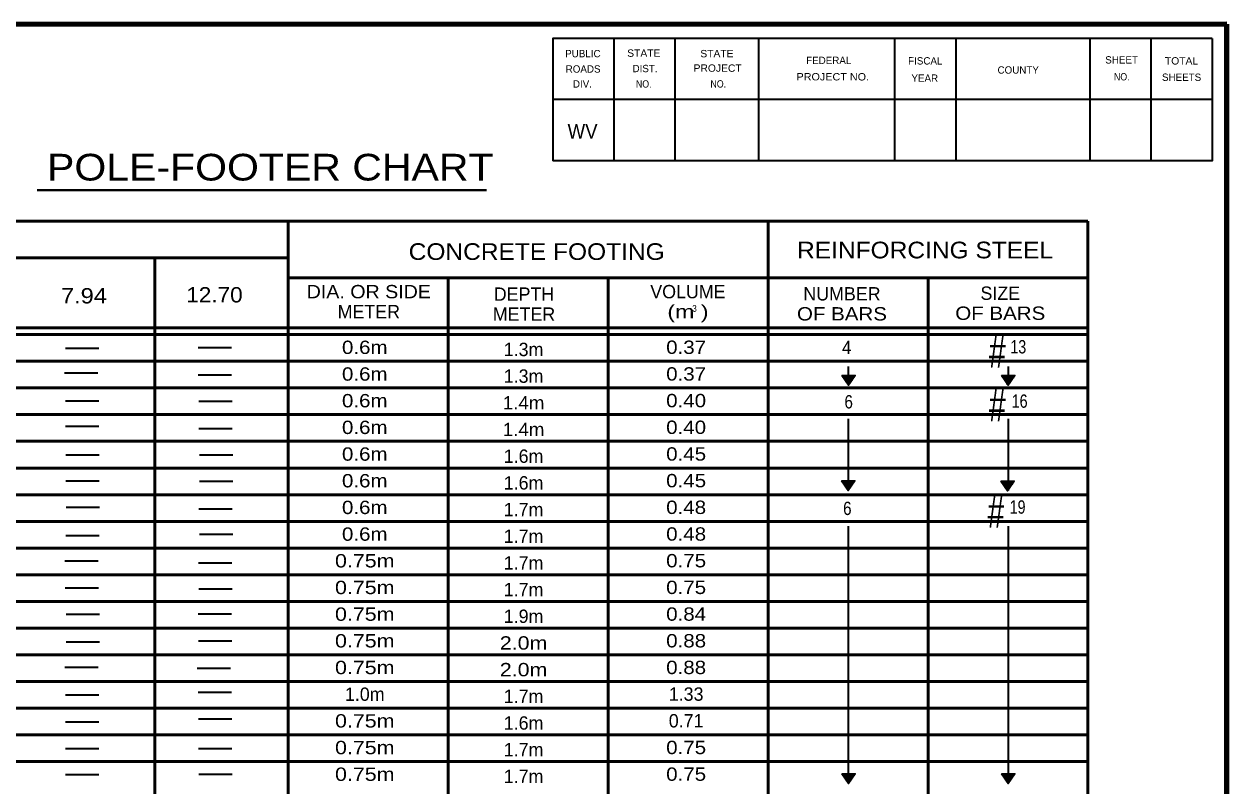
# Model space of a CAD drawing. Extents: x -711 to 145, y 25 to 569.
# Drawn here: x -112 to 138.1, y 404.4 to 562.7 of the extents above; entities that cross this region are included whole.
import ezdxf
from ezdxf.enums import TextEntityAlignment as Align

# ---------------------------------------------------------------- set-up
doc = ezdxf.new("R2010")
doc.units = 0
doc.header["$LTSCALE"] = 1.1
doc.layers.add('1', color=7, linetype='Continuous', lineweight=53)
doc.layers.add('61', color=7, linetype='Continuous', lineweight=35)

msp = doc.modelspace()

# ---------------------------------------------------------------- linework, layer by layer
at = {"layer": '1', "lineweight": 158}
msp.add_line((138.105, 36.575), (138.105, 562.675), dxfattribs=at)
at = {"layer": '1', "lineweight": 13}
msp.add_line((138.105, 36.575), (138.105, 562.675), dxfattribs=at)
at = {"layer": '1', "lineweight": 40}
msp.add_line((-109.311, 528.153), (-15.861, 528.153), dxfattribs=at)
at = {"layer": '1'}
for p, q in [((-251.147, 521.717), (-44.796, 521.717)), ((-57.107, 521.717), (-57.107, 281.939)), ((-57.097, 521.717), (109.213, 521.717)), ((42.685, 521.717), (42.685, 281.939)), ((109.213, 521.717), (109.213, 281.939)), ((-251.147, 514.094), (-57.107, 514.094)), ((-84.827, 514.094), (-84.827, 281.939)), ((-57.107, 509.936), (109.213, 509.936)), ((-23.843, 509.936), (-23.843, 281.939)), ((9.421, 509.936), (9.421, 281.939)), ((75.949, 509.936), (75.949, 281.939)), ((-251.147, 499.541), (109.194, 499.541)), ((-251.147, 498.155), (109.194, 498.155)), ((-251.147, 492.611), (109.194, 492.611)), ((-251.147, 487.067), (109.194, 487.067)), ((-251.147, 481.523), (109.194, 481.523)), ((-251.147, 475.979), (109.194, 475.979)), ((-251.147, 470.435), (109.194, 470.435)), ((-251.147, 464.891), (109.194, 464.891)), ((-251.147, 459.347), (109.194, 459.347)), ((-251.147, 453.803), (109.194, 453.803)), ((-251.147, 448.259), (109.194, 448.259)), ((-251.147, 442.715), (109.194, 442.715)), ((-251.147, 437.171), (109.194, 437.171)), ((-251.147, 431.627), (109.194, 431.627)), ((-251.147, 426.083), (109.194, 426.083)), ((-251.147, 420.539), (109.194, 420.539)), ((-251.147, 414.995), (109.194, 414.995)), ((-251.147, 409.451), (109.194, 409.451))]:
    msp.add_line(p, q, dxfattribs=at)
at = {"layer": '1', "lineweight": 35}
for p, q in [((-103.41, 495.341), (-96.48, 495.341)), ((-75.797, 495.447), (-68.867, 495.447)), ((59.317, 491.516), (59.317, 488.084)), ((92.581, 491.516), (92.581, 488.084)), ((-103.584, 490.23), (-96.654, 490.23)), ((-75.797, 489.804), (-68.867, 489.804)), ((-103.373, 484.373), (-96.443, 484.373)), ((-75.658, 484.339), (-68.728, 484.339)), ((59.317, 480.647), (59.317, 465.773)), ((92.581, 480.647), (92.581, 465.773)), ((-103.369, 479.156), (-96.439, 479.156)), ((-75.658, 478.659), (-68.728, 478.659)), ((-103.301, 473.16), (-96.371, 473.16)), ((-75.519, 473.16), (-68.589, 473.16)), ((-103.339, 467.766), (-96.409, 467.766)), ((-75.519, 467.728), (-68.589, 467.728)), ((-103.23, 462.301), (-96.3, 462.301)), ((-75.692, 461.981), (-68.762, 461.981)), ((59.317, 458.336), (59.317, 404.848)), ((92.581, 458.336), (92.581, 404.848)), ((-103.301, 456.444), (-96.371, 456.444)), ((-75.553, 456.692), (-68.623, 456.692)), ((-103.516, 451.155), (-96.586, 451.155)), ((-75.73, 450.73), (-68.8, 450.73)), ((-103.478, 445.513), (-96.548, 445.513)), ((-75.658, 445.303), (-68.728, 445.303)), ((-103.234, 440.048), (-96.304, 440.048)), ((-75.835, 440.119), (-68.905, 440.119)), ((-103.234, 434.3), (-96.304, 434.3)), ((-75.73, 434.511), (-68.8, 434.511)), ((-103.55, 429.046), (-96.62, 429.046)), ((-76.046, 428.835), (-69.116, 428.835)), ((-103.41, 423.298), (-96.48, 423.298)), ((-75.835, 423.862), (-68.905, 423.862)), ((-75.764, 418.325), (-68.834, 418.325)), ((-103.407, 417.69), (-96.477, 417.69)), ((-103.41, 412.153), (-96.48, 412.153)), ((-75.767, 412.153), (-68.837, 412.153)), ((-103.41, 406.755), (-96.48, 406.755)), ((-75.696, 406.793), (-68.766, 406.793))]:
    msp.add_line(p, q, dxfattribs=at)
at = {"layer": '1', "lineweight": 158}
msp.add_lwpolyline([(138.105, 562.675), (-653.595, 562.575), (-653.495, 36.575)], dxfattribs=at)
at = {"layer": '1', "lineweight": 35}
for points in [[(58.038, 489.639), (60.81, 489.639), (59.424, 487.626)], [(91.203, 489.639), (93.975, 489.639), (92.589, 487.626)], [(57.944, 467.781), (60.716, 467.781), (59.33, 465.768)], [(91.109, 467.687), (93.88, 467.687), (92.495, 465.674)], [(58.038, 406.916), (60.81, 406.916), (59.424, 404.903)], [(91.203, 406.916), (93.975, 406.916), (92.589, 404.903)]]:
    msp.add_lwpolyline(points, close=True, dxfattribs=at)
for points in [[(58.297, 489.441), (58.721, 489.488), (59.381, 489.347), (59.852, 489.441), (60.04, 489.441), (60.323, 489.535), (60.511, 489.488), (59.664, 489.3), (59.287, 489.629), (59.334, 489.3), (59.334, 489.394), (59.758, 489.535), (60.276, 489.535), (60.182, 489.441), (59.192, 489.488), (58.816, 489.441), (58.58, 489.347), (58.768, 489.205), (58.863, 489.017), (58.957, 488.829), (59.004, 488.687), (59.145, 488.499), (59.569, 488.169), (59.569, 487.886), (59.428, 488.169), (59.334, 488.405), (59.145, 488.64), (58.957, 488.876), (58.674, 489.111), (58.486, 489.441), (58.674, 489.158), (58.768, 488.829), (58.91, 488.64), (59.004, 488.546), (59.239, 488.405), (59.381, 488.31), (59.475, 488.122), (59.522, 488.075), (59.381, 488.122), (59.239, 488.357), (59.239, 488.122), (59.758, 488.263), (60.464, 489.488), (60.511, 489.488), (60.464, 489.3), (60.276, 488.97), (60.087, 488.687), (60.04, 488.687), (59.852, 488.357), (59.71, 488.075), (59.569, 487.886), (59.475, 487.886), (60.559, 489.488), (60.511, 489.347), (60.653, 489.441), (60.464, 489.205), (60.182, 488.876), (60.04, 488.781), (59.852, 488.452), (59.758, 488.405), (59.616, 488.593), (59.428, 488.593), (59.239, 488.593), (59.569, 488.31), (59.522, 488.452), (59.287, 488.31), (59.758, 488.923), (59.664, 488.734), (59.616, 488.64), (59.428, 488.64), (59.239, 488.781), (59.192, 489.064), (59.098, 489.158), (59.004, 489.252), (59.475, 489.394), (59.664, 489.111), (59.71, 489.205), (59.334, 489.017), (59.569, 489.064), (59.852, 489.252), (59.946, 489.158), (59.616, 488.876), (59.616, 489.158), (59.428, 489.347), (59.004, 489.205), (58.91, 488.64), (59.475, 489.111), (59.71, 489.064), (59.852, 489.158), (59.993, 489.3), (59.805, 488.829), (59.758, 488.546), (60.087, 488.97), (59.852, 488.923), (60.135, 489.3), (59.993, 489.111), (59.946, 489.064), (59.664, 488.781), (59.616, 488.829), (59.522, 489.017), (59.475, 489.252)], [(59.475, 489.252), (59.145, 489.017), (59.334, 488.876), (58.768, 489.205), (58.768, 489.3), (59.051, 488.829), (59.522, 488.876), (59.287, 488.734), (59.569, 488.781), (59.993, 489.205), (60.229, 489.252), (60.229, 489.3), (60.087, 489.017), (59.664, 488.499), (59.569, 488.122), (58.863, 489.252), (58.863, 489.441), (58.957, 489.252), (58.863, 488.687), (59.381, 488.405), (59.192, 487.933), (59.428, 488.028), (59.239, 488.64), (59.852, 489.252), (59.334, 489.111)], [(91.462, 489.441), (91.886, 489.488), (92.545, 489.347), (93.016, 489.441), (93.205, 489.441), (93.488, 489.535), (93.676, 489.488), (92.828, 489.3), (92.451, 489.629), (92.498, 489.3), (92.498, 489.394), (92.922, 489.535), (93.44, 489.535), (93.346, 489.441), (92.357, 489.488), (91.98, 489.441), (91.744, 489.347), (91.933, 489.205), (92.027, 489.017), (92.121, 488.829), (92.168, 488.687), (92.31, 488.499), (92.734, 488.169), (92.734, 487.886), (92.592, 488.169), (92.498, 488.405), (92.31, 488.64), (92.121, 488.876), (91.839, 489.111), (91.65, 489.441), (91.839, 489.158), (91.933, 488.829), (92.074, 488.64), (92.168, 488.546), (92.404, 488.405), (92.545, 488.31), (92.639, 488.122), (92.687, 488.075), (92.545, 488.122), (92.404, 488.357), (92.404, 488.122), (92.922, 488.263), (93.629, 489.488), (93.676, 489.488), (93.629, 489.3), (93.44, 488.97), (93.252, 488.687), (93.205, 488.687), (93.016, 488.357), (92.875, 488.075), (92.734, 487.886), (92.639, 487.886), (93.723, 489.488), (93.676, 489.347), (93.817, 489.441), (93.629, 489.205), (93.346, 488.876), (93.205, 488.781), (93.016, 488.452), (92.922, 488.405), (92.781, 488.593), (92.592, 488.593), (92.404, 488.593), (92.734, 488.31), (92.687, 488.452), (92.451, 488.31), (92.922, 488.923), (92.828, 488.734), (92.781, 488.64), (92.592, 488.64), (92.404, 488.781), (92.357, 489.064), (92.263, 489.158), (92.168, 489.252), (92.639, 489.394), (92.828, 489.111), (92.875, 489.205), (92.498, 489.017), (92.734, 489.064), (93.016, 489.252), (93.111, 489.158), (92.781, 488.876), (92.781, 489.158), (92.592, 489.347), (92.168, 489.205), (92.074, 488.64), (92.639, 489.111), (92.875, 489.064), (93.016, 489.158), (93.158, 489.3), (92.969, 488.829), (92.922, 488.546), (93.252, 488.97), (93.016, 488.923), (93.299, 489.3), (93.158, 489.111), (93.111, 489.064), (92.828, 488.781), (92.781, 488.829), (92.687, 489.017), (92.639, 489.252)], [(92.639, 489.252), (92.31, 489.017), (92.498, 488.876), (91.933, 489.205), (91.933, 489.3), (92.215, 488.829), (92.687, 488.876), (92.451, 488.734), (92.734, 488.781), (93.158, 489.205), (93.393, 489.252), (93.393, 489.3), (93.252, 489.017), (92.828, 488.499), (92.734, 488.122), (92.027, 489.252), (92.027, 489.441), (92.121, 489.252), (92.027, 488.687), (92.545, 488.405), (92.357, 487.933), (92.592, 488.028), (92.404, 488.64), (93.016, 489.252), (92.498, 489.111)], [(58.203, 467.582), (58.627, 467.63), (59.287, 467.488), (59.758, 467.582), (59.946, 467.582), (60.229, 467.677), (60.417, 467.63), (59.569, 467.441), (59.192, 467.771), (59.239, 467.441), (59.239, 467.535), (59.663, 467.677), (60.182, 467.677), (60.087, 467.582), (59.098, 467.63), (58.721, 467.582), (58.486, 467.488), (58.674, 467.347), (58.768, 467.159), (58.863, 466.97), (58.91, 466.829), (59.051, 466.64), (59.475, 466.311), (59.475, 466.028), (59.334, 466.311), (59.239, 466.546), (59.051, 466.782), (58.863, 467.017), (58.58, 467.253), (58.391, 467.582), (58.58, 467.3), (58.674, 466.97), (58.816, 466.782), (58.91, 466.687), (59.145, 466.546), (59.287, 466.452), (59.381, 466.263), (59.428, 466.216), (59.287, 466.263), (59.145, 466.499), (59.145, 466.263), (59.663, 466.405), (60.37, 467.63), (60.417, 467.63), (60.37, 467.441), (60.182, 467.111), (59.993, 466.829), (59.946, 466.829), (59.758, 466.499), (59.616, 466.216), (59.475, 466.028), (59.381, 466.028), (60.464, 467.63), (60.417, 467.488), (60.559, 467.582), (60.37, 467.347), (60.087, 467.017), (59.946, 466.923), (59.758, 466.593), (59.663, 466.546), (59.522, 466.735), (59.334, 466.735), (59.145, 466.735), (59.475, 466.452), (59.428, 466.593), (59.192, 466.452), (59.663, 467.064), (59.569, 466.876), (59.522, 466.782), (59.334, 466.782), (59.145, 466.923), (59.098, 467.206), (59.004, 467.3), (58.91, 467.394), (59.381, 467.535), (59.569, 467.253), (59.616, 467.347), (59.239, 467.159), (59.475, 467.206), (59.758, 467.394), (59.852, 467.3), (59.522, 467.017), (59.522, 467.3), (59.334, 467.488), (58.91, 467.347), (58.816, 466.782), (59.381, 467.253), (59.616, 467.206), (59.758, 467.3), (59.899, 467.441), (59.71, 466.97), (59.663, 466.687), (59.993, 467.111), (59.758, 467.064), (60.04, 467.441), (59.899, 467.253), (59.852, 467.206), (59.569, 466.923), (59.522, 466.97), (59.428, 467.159), (59.381, 467.394)], [(59.381, 467.394), (59.051, 467.159), (59.239, 467.017), (58.674, 467.347), (58.674, 467.441), (58.957, 466.97), (59.428, 467.017), (59.192, 466.876), (59.475, 466.923), (59.899, 467.347), (60.135, 467.394), (60.135, 467.441), (59.993, 467.159), (59.569, 466.64), (59.475, 466.263), (58.768, 467.394), (58.768, 467.582), (58.863, 467.394), (58.768, 466.829), (59.287, 466.546), (59.098, 466.075), (59.334, 466.169), (59.145, 466.782), (59.758, 467.394), (59.239, 467.253)], [(91.368, 467.488), (91.791, 467.535), (92.451, 467.394), (92.922, 467.488), (93.111, 467.488), (93.393, 467.582), (93.582, 467.535), (92.734, 467.347), (92.357, 467.677), (92.404, 467.347), (92.404, 467.441), (92.828, 467.582), (93.346, 467.582), (93.252, 467.488), (92.263, 467.535), (91.886, 467.488), (91.65, 467.394), (91.839, 467.253), (91.933, 467.064), (92.027, 466.876), (92.074, 466.735), (92.216, 466.546), (92.639, 466.216), (92.639, 465.934), (92.498, 466.216), (92.404, 466.452), (92.216, 466.687), (92.027, 466.923), (91.744, 467.159), (91.556, 467.488), (91.744, 467.206), (91.839, 466.876), (91.98, 466.687), (92.074, 466.593), (92.31, 466.452), (92.451, 466.358), (92.545, 466.169), (92.593, 466.122), (92.451, 466.169), (92.31, 466.405), (92.31, 466.169), (92.828, 466.311), (93.535, 467.535), (93.582, 467.535), (93.535, 467.347), (93.346, 467.017), (93.158, 466.735), (93.111, 466.735), (92.922, 466.405), (92.781, 466.122), (92.639, 465.934), (92.545, 465.934), (93.629, 467.535), (93.582, 467.394), (93.723, 467.488), (93.535, 467.253), (93.252, 466.923), (93.111, 466.829), (92.922, 466.499), (92.828, 466.452), (92.687, 466.64), (92.498, 466.64), (92.31, 466.64), (92.639, 466.358), (92.593, 466.499), (92.357, 466.358), (92.828, 466.97), (92.734, 466.782), (92.687, 466.687), (92.498, 466.687), (92.31, 466.829), (92.263, 467.111), (92.169, 467.206), (92.074, 467.3), (92.545, 467.441), (92.734, 467.159), (92.781, 467.253), (92.404, 467.064), (92.639, 467.111), (92.922, 467.3), (93.016, 467.206), (92.687, 466.923), (92.687, 467.206), (92.498, 467.394), (92.074, 467.253), (91.98, 466.687), (92.545, 467.159), (92.781, 467.111), (92.922, 467.206), (93.064, 467.347), (92.875, 466.876), (92.828, 466.593), (93.158, 467.017), (92.922, 466.97), (93.205, 467.347), (93.064, 467.159), (93.016, 467.111), (92.734, 466.829), (92.687, 466.876), (92.593, 467.064), (92.545, 467.3)], [(92.545, 467.3), (92.216, 467.064), (92.404, 466.923), (91.839, 467.253), (91.839, 467.347), (92.121, 466.876), (92.593, 466.923), (92.357, 466.782), (92.639, 466.829), (93.064, 467.253), (93.299, 467.3), (93.299, 467.347), (93.158, 467.064), (92.734, 466.546), (92.639, 466.169), (91.933, 467.3), (91.933, 467.488), (92.027, 467.3), (91.933, 466.735), (92.451, 466.452), (92.263, 465.981), (92.498, 466.075), (92.31, 466.687), (92.922, 467.3), (92.404, 467.159)], [(58.297, 406.718), (58.721, 406.765), (59.381, 406.624), (59.852, 406.718), (60.04, 406.718), (60.323, 406.812), (60.511, 406.765), (59.664, 406.577), (59.287, 406.906), (59.334, 406.577), (59.334, 406.671), (59.758, 406.812), (60.276, 406.812), (60.182, 406.718), (59.192, 406.765), (58.816, 406.718), (58.58, 406.624), (58.768, 406.482), (58.863, 406.294), (58.957, 406.106), (59.004, 405.964), (59.145, 405.776), (59.569, 405.446), (59.569, 405.163), (59.428, 405.446), (59.334, 405.682), (59.145, 405.917), (58.957, 406.153), (58.674, 406.388), (58.486, 406.718), (58.674, 406.435), (58.768, 406.106), (58.91, 405.917), (59.004, 405.823), (59.239, 405.682), (59.381, 405.587), (59.475, 405.399), (59.522, 405.352), (59.381, 405.399), (59.239, 405.634), (59.239, 405.399), (59.758, 405.54), (60.464, 406.765), (60.511, 406.765), (60.464, 406.577), (60.276, 406.247), (60.087, 405.964), (60.04, 405.964), (59.852, 405.634), (59.71, 405.352), (59.569, 405.163), (59.475, 405.163), (60.559, 406.765), (60.511, 406.624), (60.653, 406.718), (60.464, 406.482), (60.182, 406.153), (60.04, 406.058), (59.852, 405.729), (59.758, 405.682), (59.616, 405.87), (59.428, 405.87), (59.239, 405.87), (59.569, 405.587), (59.522, 405.729), (59.287, 405.587), (59.758, 406.2), (59.664, 406.011), (59.616, 405.917), (59.428, 405.917), (59.239, 406.058), (59.192, 406.341), (59.098, 406.435), (59.004, 406.53), (59.475, 406.671), (59.664, 406.388), (59.71, 406.482), (59.334, 406.294), (59.569, 406.341), (59.852, 406.53), (59.946, 406.435), (59.616, 406.153), (59.616, 406.435), (59.428, 406.624), (59.004, 406.482), (58.91, 405.917), (59.475, 406.388), (59.71, 406.341), (59.852, 406.435), (59.993, 406.577), (59.805, 406.106), (59.758, 405.823), (60.087, 406.247), (59.852, 406.2), (60.135, 406.577), (59.993, 406.388), (59.946, 406.341), (59.664, 406.058), (59.616, 406.106), (59.522, 406.294), (59.475, 406.53)], [(59.475, 406.53), (59.145, 406.294), (59.334, 406.153), (58.768, 406.482), (58.768, 406.577), (59.051, 406.106), (59.522, 406.153), (59.287, 406.011), (59.569, 406.058), (59.993, 406.482), (60.229, 406.53), (60.229, 406.577), (60.087, 406.294), (59.664, 405.776), (59.569, 405.399), (58.863, 406.53), (58.863, 406.718), (58.957, 406.53), (58.863, 405.964), (59.381, 405.682), (59.192, 405.211), (59.428, 405.305), (59.239, 405.917), (59.852, 406.53), (59.334, 406.388)], [(91.462, 406.718), (91.886, 406.765), (92.545, 406.624), (93.016, 406.718), (93.205, 406.718), (93.488, 406.812), (93.676, 406.765), (92.828, 406.577), (92.451, 406.906), (92.498, 406.577), (92.498, 406.671), (92.922, 406.812), (93.44, 406.812), (93.346, 406.718), (92.357, 406.765), (91.98, 406.718), (91.745, 406.624), (91.933, 406.482), (92.027, 406.294), (92.121, 406.106), (92.169, 405.964), (92.31, 405.776), (92.734, 405.446), (92.734, 405.163), (92.593, 405.446), (92.498, 405.682), (92.31, 405.917), (92.121, 406.153), (91.839, 406.388), (91.65, 406.718), (91.839, 406.435), (91.933, 406.106), (92.074, 405.917), (92.169, 405.823), (92.404, 405.682), (92.545, 405.587), (92.639, 405.399), (92.687, 405.352), (92.545, 405.399), (92.404, 405.634), (92.404, 405.399), (92.922, 405.54), (93.629, 406.765), (93.676, 406.765), (93.629, 406.577), (93.44, 406.247), (93.252, 405.964), (93.205, 405.964), (93.016, 405.634), (92.875, 405.352), (92.734, 405.163), (92.639, 405.163), (93.723, 406.765), (93.676, 406.624), (93.817, 406.718), (93.629, 406.482), (93.346, 406.153), (93.205, 406.058), (93.016, 405.729), (92.922, 405.682), (92.781, 405.87), (92.593, 405.87), (92.404, 405.87), (92.734, 405.587), (92.687, 405.729), (92.451, 405.587), (92.922, 406.2), (92.828, 406.011), (92.781, 405.917), (92.593, 405.917), (92.404, 406.058), (92.357, 406.341), (92.263, 406.435), (92.169, 406.53), (92.639, 406.671), (92.828, 406.388), (92.875, 406.482), (92.498, 406.294), (92.734, 406.341), (93.016, 406.53), (93.111, 406.435), (92.781, 406.153), (92.781, 406.435), (92.593, 406.624), (92.169, 406.482), (92.074, 405.917), (92.639, 406.388), (92.875, 406.341), (93.016, 406.435), (93.158, 406.577), (92.969, 406.106), (92.922, 405.823), (93.252, 406.247), (93.016, 406.2), (93.299, 406.577), (93.158, 406.388), (93.111, 406.341), (92.828, 406.058), (92.781, 406.106), (92.687, 406.294), (92.639, 406.53)], [(92.639, 406.53), (92.31, 406.294), (92.498, 406.153), (91.933, 406.482), (91.933, 406.577), (92.216, 406.106), (92.687, 406.153), (92.451, 406.011), (92.734, 406.058), (93.158, 406.482), (93.393, 406.53), (93.393, 406.577), (93.252, 406.294), (92.828, 405.776), (92.734, 405.399), (92.027, 406.53), (92.027, 406.718), (92.121, 406.53), (92.027, 405.964), (92.545, 405.682), (92.357, 405.211), (92.593, 405.305), (92.404, 405.917), (93.016, 406.53), (92.498, 406.388)]]:
    msp.add_lwpolyline(points, dxfattribs=at)
at = {"layer": '61'}
for p, q in [((10.605, 559.675), (10.605, 534.275)), ((23.305, 559.675), (23.305, 534.275)), ((40.705, 559.675), (40.705, 534.275)), ((69.005, 559.675), (69.005, 534.275)), ((81.705, 559.675), (81.705, 534.275)), ((109.605, 559.675), (109.605, 534.275)), ((122.305, 559.675), (122.305, 534.275)), ((135.005, 546.975), (-2.095, 546.975))]:
    msp.add_line(p, q, dxfattribs=at)
for points in [[(135.005, 559.675), (-2.095, 559.675), (-2.095, 534.275)], [(135.005, 559.675), (135.005, 534.275), (-2.095, 534.275)]]:
    msp.add_lwpolyline(points, dxfattribs=at)

# ---------------------------------------------------------------- texts
at = {"layer": '1'}
for s, height, width, p in [('WV', 3.048, 0.95, (1.005, 538.875)), ('POLE-FOOTER CHART', 5.544, 1.15, (-107.24, 530.17)), ('CONCRETE FOOTING', 3.465, 1.1, (-32.043, 513.671)), ('REINFORCING STEEL', 3.465, 1.1, (48.719, 513.995)), ('7.94', 3.188, 1.15, (-104.338, 504.627)), ('12.70', 3.188, 1.1, (-78.293, 504.832))]:
    msp.add_text(s, height=height, dxfattribs=dict(at, width=width)).set_placement(p)
for s, height, width, p in [('DIA. OR SIDE', 2.772, 1.1, (-40.33, 505.695)), ('(m )', 2.772, 1.3, (26.027, 501.537)), ('3', 1.386, 0.9, (27.392, 502.889)), ('OF BARS', 2.772, 1.15, (58.055, 501.086)), ('OF BARS', 2.772, 1.15, (90.975, 501.215)), ('#', 6.653, 0.7, (90.36, 491.308)), ('0.6m', 2.772, 1.15, (-41.173, 494.127)), ('0.37', 2.772, 1.15, (25.654, 494.145)), ('4', 2.772, 0.95, (59.03, 494.093)), ('13', 2.772, 0.8, (94.717, 494.234)), ('0.6m', 2.772, 1.15, (-41.173, 488.583)), ('0.37', 2.772, 1.15, (25.654, 488.601)), ('0.6m', 2.772, 1.15, (-41.173, 483.039)), ('1.4m', 2.772, 1.05, (-8.144, 482.596)), ('0.40', 2.772, 1.15, (25.654, 483.057)), ('6', 2.772, 0.85, (59.453, 482.809)), ('#', 6.653, 0.7, (90.36, 480.165)), ('16', 2.772, 0.8, (94.999, 482.95)), ('0.6m', 2.772, 1.15, (-41.173, 477.495)), ('0.40', 2.772, 1.15, (25.654, 477.513)), ('1.4m', 2.772, 1.05, (-8.144, 477.052)), ('0.6m', 2.772, 1.15, (-41.173, 471.951)), ('0.45', 2.772, 1.15, (25.654, 471.969)), ('0.6m', 2.772, 1.15, (-41.173, 466.407)), ('0.45', 2.772, 1.15, (25.654, 466.425)), ('0.6m', 2.772, 1.15, (-41.173, 460.863)), ('0.48', 2.772, 1.15, (25.654, 460.881)), ('6', 2.772, 0.85, (59.171, 460.663)), ('#', 6.653, 0.7, (90.078, 458.019)), ('19', 2.772, 0.8, (94.576, 460.945)), ('0.6m', 2.772, 1.15, (-41.173, 455.319)), ('0.48', 2.772, 1.15, (25.654, 455.337)), ('0.75m', 2.772, 1.2, (-41.173, 449.775)), ('0.75', 2.772, 1.15, (25.654, 449.793)), ('0.75m', 2.772, 1.2, (-41.173, 444.231)), ('0.75', 2.772, 1.15, (25.654, 444.249)), ('0.75m', 2.772, 1.2, (-41.173, 438.687)), ('0.84', 2.772, 1.15, (25.654, 438.705)), ('0.75m', 2.772, 1.2, (-41.173, 433.143)), ('2.0m', 2.772, 1.2, (-8.145, 432.7)), ('0.88', 2.772, 1.15, (25.654, 433.161)), ('0.75m', 2.772, 1.2, (-41.173, 427.599)), ('0.88', 2.772, 1.15, (25.654, 427.617)), ('2.0m', 2.772, 1.2, (-8.145, 427.156)), ('0.75m', 2.772, 1.2, (-41.173, 416.511)), ('0.75m', 2.772, 1.2, (-41.173, 410.967)), ('0.75', 2.772, 1.15, (25.654, 410.985)), ('0.75m', 2.772, 1.2, (-41.173, 405.423)), ('0.75', 2.772, 1.15, (25.654, 405.441))]:
    msp.add_text(s, height=height, dxfattribs=dict(at, width=width)).set_placement(p, align=Align.CENTER)
for s, p in [('DEPTH', (-8.055, 505.179)), ('VOLUME', (26.027, 505.695)), ('NUMBER', (58.055, 505.244)), ('SIZE', (90.975, 505.373)), ('METER', (-40.33, 501.537)), ('METER', (-8.055, 501.021)), ('1.3m', (-8.144, 493.684)), ('1.3m', (-8.144, 488.14)), ('1.6m', (-8.144, 471.508)), ('1.6m', (-8.144, 465.964)), ('1.7m', (-8.144, 460.42)), ('1.7m', (-8.144, 454.876)), ('1.7m', (-8.144, 449.332)), ('1.7m', (-8.144, 443.788)), ('1.9m', (-8.144, 438.244)), ('1.0m', (-41.173, 422.055)), ('1.7m', (-8.144, 421.612)), ('1.33', (25.654, 422.073)), ('1.6m', (-8.144, 416.068)), ('0.71', (25.654, 416.529)), ('1.7m', (-8.144, 410.524)), ('1.7m', (-8.144, 404.98))]:
    msp.add_text(s, height=2.772, dxfattribs=at).set_placement(p, align=Align.CENTER)
at = {"layer": '61'}
for s, height, rotation, p in [('PUBLIC', 1.525, 0.033, (0.505, 555.775)), ('FEDERAL', 1.523, 0.007, (50.605, 554.375)), ('FISCAL', 1.525, 359.942, (71.805, 554.275)), ('SHEET', 1.525, 0.059, (112.805, 554.475)), ('ROADS', 1.525, 0.124, (0.605, 552.575)), ('DIST.', 1.525, 0.056, (14.505, 552.675)), ('COUNTY', 1.523, 0.069, (90.405, 552.375)), ('DIV.', 1.525, 359.932, (2.105, 549.475)), ('YEAR', 1.523, 0.105, (72.505, 550.675)), ('SHEETS', 1.523, 359.959, (124.605, 550.875))]:
    msp.add_text(s, height=height, rotation=rotation, dxfattribs=at).set_placement(p)
for s, rotation, width, p in [('STATE', 0.059, 1.05, (13.405, 555.875)), ('STATE', 0.059, 1.05, (28.605, 555.775)), ('TOTAL', 359.926, 1.05, (125.205, 554.275)), ('PROJECT', 359.908, 1.05, (27.205, 552.775)), ('NO.', 359.852, 0.9, (15.205, 549.475)), ('NO.', 0.225, 0.9, (30.705, 549.475)), ('PROJECT NO.', 359.922, 1.1, (48.605, 550.975)), ('NO.', 359.852, 0.9, (114.605, 550.975))]:
    msp.add_text(s, height=1.525, rotation=rotation, dxfattribs=dict(at, width=width)).set_placement(p)

doc.saveas('drawing.dxf')
